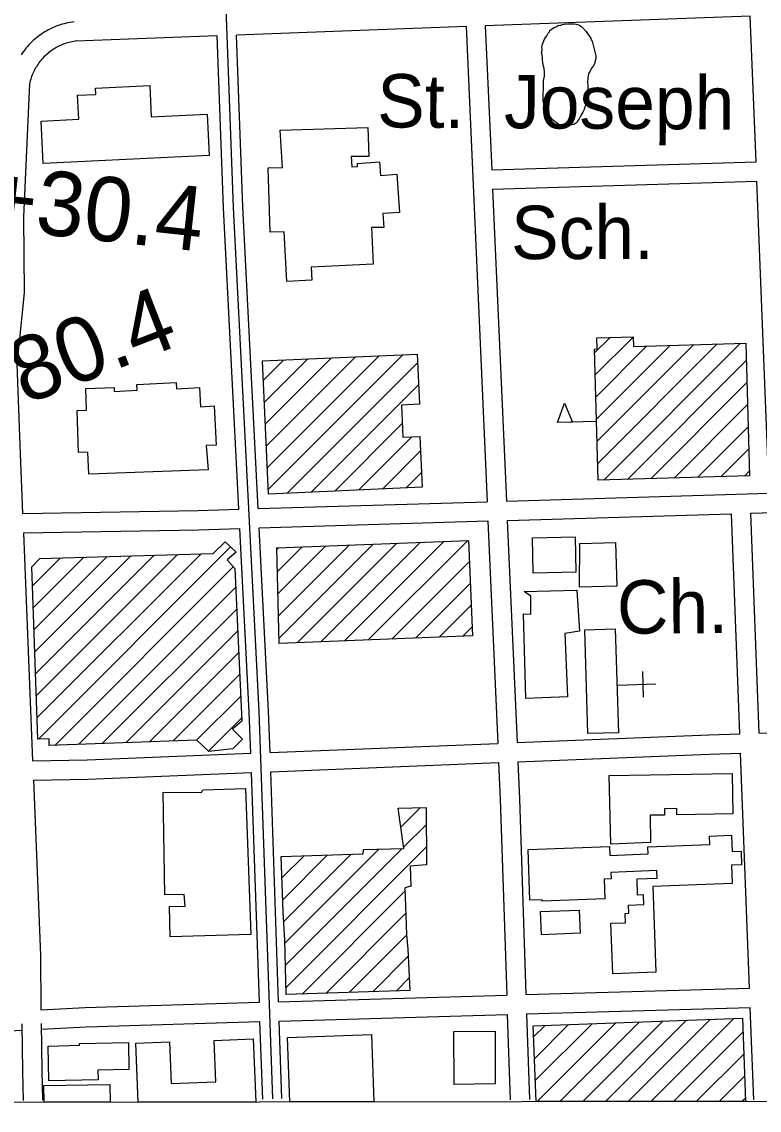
# Model space of a CAD drawing. Extents: x 3313447 to 3351316, y 703786 to 729172.
# Drawn here: x 3326147 to 3327294, y 709166 to 710857 of the extents above; entities that cross this region are included whole.
import ezdxf

# ---------------------------------------------------------------- set-up
doc = ezdxf.new("R2010")
doc.units = 0
for name, color, linetype in [('V-BLDG-IDEN', 7, 'Continuous'), ('V-BLDG-OTLN', 7, 'Continuous'), ('V-GRID-FRAM', 7, 'Continuous'), ('V-ROAD-CNTR', 7, 'Continuous'), ('V-SITE-OTLN', 7, 'Continuous'), ('V-SITE-OTLN-IDEN', 7, 'Continuous'), ('V-SITE-VEGE', 7, 'Continuous'), ('V-SURV-IDEN', 7, 'Continuous')]:
    doc.layers.add(name, color=color, linetype=linetype)

msp = doc.modelspace()

# ---------------------------------------------------------------- linework, layer by layer
at = {"layer": 'V-BLDG-OTLN'}
for p, q in [((3327037.8, 710343), (3327061.8, 710367)), ((3327038.8, 710308.6), (3327097.6, 710367.5)), ((3327040.7, 710239.9), (3327155.6, 710354.7)), ((3327041.7, 710205.5), (3327192, 710355.8)), ((3327042.7, 710171.2), (3327228.4, 710356.8)), ((3327052.2, 710145.3), (3327264.8, 710357.9)), ((3326528.8, 710164.4), (3326702.9, 710338.5)), ((3326530.3, 710130.5), (3326739.9, 710340.1)), ((3327039.8, 710274.3), (3327119.2, 710353.7)), ((3326522.7, 710299.8), (3326554.9, 710331.9)), ((3326524.2, 710265.9), (3326591.9, 710333.6)), ((3326525.7, 710232.1), (3326628.9, 710335.2)), ((3326527.2, 710198.2), (3326665.9, 710336.9)), ((3326559.9, 710124.8), (3326762.7, 710327.7)), ((3327088.7, 710146.4), (3327273.5, 710331.3)), ((3326596.9, 710126.5), (3326764.3, 710293.8)), ((3327125.1, 710147.4), (3327274.5, 710296.9)), ((3327161.5, 710148.5), (3327275.5, 710262.5)), ((3327040.3, 710236.3), (3326980.3, 710234.6)), ((3326633.9, 710128.1), (3326738.8, 710233)), ((3327197.9, 710149.5), (3327276.5, 710228.2)), ((3326670.9, 710129.8), (3326753.5, 710212.4)), ((3326707.9, 710131.4), (3326767.3, 710190.8)), ((3327234.3, 710150.6), (3327277.5, 710193.8)), ((3326744.9, 710133.1), (3326768.8, 710156.9)), ((3327270.7, 710151.6), (3327278.5, 710159.5)), ((3326648.9, 709895.3), (3326803.8, 710050.1)), ((3326685.7, 709896.8), (3326840.5, 710051.6)), ((3326173.1, 709742.7), (3326471.9, 710041.5)), ((3326543.7, 710037.6), (3326546.2, 710040.1)), ((3326544.6, 710003.1), (3326583, 710041.5)), ((3326545.5, 709968.7), (3326619.8, 710043)), ((3326546.4, 709934.2), (3326656.6, 710044.4)), ((3326547.3, 709899.7), (3326693.4, 710045.8)), ((3326575.2, 709892.3), (3326730.2, 710047.3)), ((3326612.1, 709893.8), (3326767, 710048.7)), ((3326163.9, 709980.9), (3326207.3, 710024.4)), ((3326165.1, 709946.8), (3326243.7, 710025.4)), ((3326166.2, 709912.6), (3326280.2, 710026.5)), ((3326167.4, 709878.4), (3326316.6, 710027.6)), ((3326168.6, 709844.2), (3326353, 710028.6)), ((3326169.8, 709810), (3326389.4, 710029.7)), ((3326170.9, 709775.9), (3326425.9, 710030.8)), ((3326722.6, 709898.2), (3326843.2, 710018.9)), ((3326198.8, 709733), (3326476.1, 710010.3)), ((3326759.4, 709899.7), (3326844.6, 709984.9)), ((3326235.5, 709734.4), (3326479.8, 709978.7)), ((3326796.2, 709901.2), (3326846.1, 709951)), ((3326272.2, 709735.7), (3326481.4, 709944.9)), ((3326833.1, 709902.7), (3326847.5, 709917.1)), ((3326309, 709737.1), (3326482.9, 709911.1)), ((3326345.7, 709738.4), (3326484.5, 709877.3)), ((3326382.4, 709739.8), (3326486, 709843.5)), ((3326419.1, 709741.1), (3326487.6, 709809.7)), ((3326437.3, 709724), (3326489.1, 709775.9)), ((3326736.6, 709606), (3326767, 709636.4)), ((3326740.8, 709574.8), (3326776.2, 709610.2)), ((3326551.8, 709527.2), (3326586.1, 709561.6)), ((3326553, 709493), (3326622.7, 709562.8)), ((3326554.5, 709459.2), (3326659.2, 709563.9)), ((3326556.2, 709425.6), (3326702.3, 709571.7)), ((3326557.2, 709391.2), (3326738.6, 709572.6)), ((3326558.1, 709356.8), (3326776.4, 709575.1)), ((3326750.5, 709513.8), (3326752, 709515.3)), ((3326583.1, 709346.4), (3326742.9, 709506.2)), ((3326619.7, 709347.6), (3326744.2, 709472.1)), ((3326656.2, 709348.8), (3326745.6, 709438.2)), ((3326692.8, 709350), (3326748, 709405.3)), ((3326729.3, 709351.2), (3326749.6, 709371.5)), ((3326942.4, 709297.2), (3327267.5, 709308.9)), ((3327054.7, 709179.8), (3327180.7, 709305.8)), ((3327090.1, 709179.8), (3327217.4, 709307.1)), ((3327125.5, 709179.9), (3327254.1, 709308.5)), ((3327267.5, 709308.9), (3327272.2, 709180.1)), ((3326946.7, 709179.6), (3326942.4, 709297.2)), ((3326943, 709280.2), (3326960.7, 709297.9)), ((3326944.2, 709246.1), (3326997.3, 709299.2)), ((3326945.5, 709212), (3327034, 709300.5)), ((3326948.5, 709179.6), (3327070.7, 709301.8)), ((3326983.9, 709179.7), (3327107.4, 709303.2)), ((3327019.3, 709179.7), (3327144.1, 709304.5)), ((3326324.6, 709270), (3326376.7, 709272.2)), ((3326376.7, 709272.2), (3326379.4, 709207.4)), ((3326446.5, 709274.5), (3326506.8, 709277)), ((3326449.1, 709210.2), (3326446.5, 709274.5)), ((3326506.8, 709277), (3326510.9, 709179)), ((3326560.2, 709278.9), (3326690.7, 709283.7)), ((3326563.9, 709179.1), (3326560.2, 709278.9)), ((3326690.7, 709283.7), (3326694.6, 709179.2)), ((3327160.9, 709179.9), (3327268.3, 709287.3)), ((3326328.3, 709178.7), (3326324.6, 709270)), ((3327196.3, 709180), (3327269.6, 709253.2)), ((3326181.7, 709204.5), (3326284.4, 709205.9)), ((3326182.1, 709178.5), (3326181.7, 709204.5)), ((3326284.4, 709205.9), (3326284.8, 709178.6)), ((3326379.4, 709207.4), (3326449.1, 709210.2)), ((3327231.7, 709180), (3327270.8, 709219.1)), ((3326284.8, 709178.6), (3326182.1, 709178.5)), ((3326510.9, 709179), (3326328.3, 709178.7)), ((3326694.6, 709179.2), (3326563.9, 709179.1)), ((3327272.2, 709180.1), (3326946.7, 709179.6)), ((3327267.1, 709180.1), (3327272, 709185))]:
    msp.add_line(p, q, dxfattribs=at)
for points in [[(3326438.8, 710649.7), (3326180.4, 710637.4), (3326177.2, 710703.2), (3326235.9, 710706), (3326234.1, 710743.2), (3326262.3, 710744.6), (3326261.8, 710754.4), (3326346.1, 710758.4), (3326348.4, 710709.9), (3326435.7, 710714.1)], [(3326548.9, 710689), (3326685.4, 710693.3), (3326686.8, 710648.3), (3326659.1, 710648.2), (3326660.2, 710632), (3326669.4, 710632.6), (3326669.1, 710637.3), (3326703.4, 710639.7), (3326704.9, 710618.8), (3326730.2, 710620.6), (3326734.3, 710561.3), (3326708.4, 710559.5), (3326709.9, 710537.8), (3326691.1, 710537.6), (3326693.7, 710480.7), (3326597.4, 710476.2), (3326598.3, 710455.8), (3326559.5, 710454), (3326555.4, 710531.1), (3326533.2, 710530.4), (3326530.1, 710630.4), (3326552.5, 710631.1)], [(3327272.8, 710358.1), (3327278.7, 710151.9), (3327043.5, 710145.1), (3327037.6, 710348.9), (3327041.5, 710349), (3327041, 710366.4), (3327097.6, 710368), (3327098, 710353.1)], [(3326769.8, 710134.2), (3326530.6, 710123.5), (3326521.4, 710330.4), (3326762.1, 710341.1), (3326765.6, 710263), (3326737.6, 710261.8), (3326739.8, 710211.8), (3326766.3, 710213)], [(3326437.1, 710161), (3326251.3, 710154.6), (3326250, 710188.7), (3326235.7, 710188.2), (3326233.6, 710253.6), (3326248, 710254.1), (3326246.9, 710287.5), (3326290.8, 710288.9), (3326290.8, 710283.1), (3326326.5, 710284.9), (3326326, 710293.7), (3326387.2, 710296.8), (3326387.7, 710287.1), (3326423.7, 710289), (3326425.2, 710259.3), (3326446.4, 710260.4), (3326449.5, 710199.7), (3326433.9, 710198.8)], [(3326980.3, 710234.6), (3326991, 710264.9), (3327003.4, 710235.2)], [(3326543.7, 710040), (3326841.8, 710051.6), (3326848.1, 709903.3), (3326547.5, 709891.2)], [(3326941, 710055.5), (3327007.5, 710057), (3327008.8, 710002.1), (3326942.1, 710000.6)], [(3326172.1, 709742.6), (3326162.9, 710010.7), (3326175.3, 710023.4), (3326444.7, 710031.3), (3326463.6, 710049.1), (3326480.8, 710033.4), (3326466.4, 710021.4), (3326478.5, 710007.7), (3326489.4, 709770.5), (3326475.1, 709758.4), (3326490.3, 709742.8), (3326475.3, 709727.5), (3326437.9, 709723.5), (3326419.4, 709741.2), (3326190, 709732.7), (3326189.6, 709743.2)], [(3327014.6, 710046.6), (3327070.4, 710048.2), (3327072.4, 709980.4), (3327014.4, 709978.7)], [(3326930.7, 709805.9), (3326927.4, 709937.2), (3326938.7, 709937), (3326938.4, 709964.9), (3326928.5, 709972.3), (3327010.2, 709974.3), (3327014.5, 709910.5), (3326991.4, 709906.7), (3326995.5, 709808.2)], [(3327070, 709913.9), (3327074.7, 709752.7), (3327027.1, 709751.3), (3327022.4, 709912.8)], [(3327063, 709579.6), (3327060.3, 709686.4), (3327251.8, 709689.3), (3327252.8, 709626.6), (3327165.6, 709625.3), (3327165.6, 709634.7), (3327146.4, 709634.6), (3327146.5, 709624.6), (3327124.2, 709624.5), (3327124.5, 709582.3)], [(3326428.7, 709663.8), (3326495.2, 709666), (3326503.3, 709438.9), (3326378.2, 709435.4), (3326376.7, 709482.7), (3326401.1, 709483.2), (3326399.9, 709501.1), (3326369.9, 709500.9), (3326366.9, 709660.5), (3326426.5, 709659.7)], [(3326550.6, 709560.4), (3326677.9, 709564.6), (3326678.3, 709571.1), (3326741.1, 709572.6), (3326732.6, 709635.5), (3326776.1, 709636.6), (3326776.6, 709547.3), (3326751, 709545.3), (3326752, 709514.2), (3326742.7, 709511.6), (3326745.5, 709439.2), (3326747.6, 709416.1), (3326750.5, 709351.9), (3326558.4, 709345.6), (3326556.1, 709430.4), (3326553.6, 709474.2)], [(3326934.4, 709571.3), (3327060.9, 709576), (3327061.5, 709562), (3327120.9, 709564.2), (3327120.5, 709575.4), (3327216.7, 709579), (3327216.2, 709592), (3327250.6, 709593.3), (3327251.6, 709567.9), (3327265.4, 709568.4), (3327266.2, 709547.4), (3327250.8, 709546.9), (3327251.8, 709518.1), (3327128.2, 709513.5), (3327133.1, 709380.7), (3327066, 709378.2), (3327063.1, 709456.5), (3327085.8, 709457.3), (3327085.2, 709471.9), (3327091.1, 709472.1), (3327090.7, 709484.7), (3327114.5, 709485.6), (3327114, 709500.8), (3327104.6, 709500.4), (3327103.7, 709525.6), (3327135, 709526.8), (3327134.5, 709538.3), (3327063.2, 709535.7), (3327063.5, 709525.6), (3327052.4, 709525.2), (3327053.5, 709494.5), (3326956.4, 709490.9), (3326956.3, 709493.2), (3326937.3, 709492.4)], [(3327015.5, 709441.1), (3326955, 709438.8), (3326953.6, 709474.6), (3327013.8, 709476.9)], [(3326819.3, 709206), (3326818.9, 709288.6), (3326883, 709288.9), (3326883.4, 709207.1)], [(3326265.9, 709213.3), (3326189.3, 709211.6), (3326188.1, 709265.8), (3326237, 709266.9), (3326236.9, 709269.7), (3326313, 709271.4), (3326313.9, 709229.5), (3326265.6, 709228.4)]]:
    msp.add_lwpolyline(points, close=True, dxfattribs=at)
at = {"layer": 'V-GRID-FRAM'}
msp.add_lwpolyline([(3317576.9, 727351), (3317595.4, 709166), (3349105.8, 709211.8), (3349071.4, 727396.8), (3317576.9, 727351)], dxfattribs=at)
at = {"layer": 'V-ROAD-CNTR'}
for points in [[(3326425.2, 711947.6), (3326476, 710569.1), (3326516, 709785.5), (3326536.8, 709183.7)], [(3327279.7, 710866.4), (3326867.9, 710851.3)], [(3327288.7, 710639.7), (3327279.7, 710866.4)], [(3326228.9, 710857.4), (3326225.9, 710857), (3326222.7, 710856.5), (3326219.5, 710855.9), (3326216.3, 710855.2), (3326213.2, 710854.5), (3326210, 710853.6), (3326206.9, 710852.6), (3326203.9, 710851.6), (3326200.8, 710850.5), (3326197.8, 710849.2), (3326194.8, 710847.9), (3326191.9, 710846.6), (3326189, 710845.1), (3326186.1, 710843.5), (3326183.3, 710841.9), (3326180.5, 710840.2), (3326177.8, 710838.4), (3326175.1, 710836.6), (3326172.5, 710834.6), (3326170, 710832.6), (3326167.5, 710830.5), (3326165, 710828.4), (3326162.7, 710826.1), (3326160.3, 710823.9), (3326158.1, 710821.5), (3326155.9, 710819.1), (3326153.8, 710816.6), (3326151.8, 710814.1), (3326149.8, 710811.5), (3326147.9, 710808.9), (3326146.1, 710806.2)], [(3326837.9, 710850.2), (3326769.7, 710847.7), (3326481.1, 710836.9)], [(3326837.9, 710850.2), (3326870.6, 710111.6)], [(3326867.9, 710851.3), (3326877.8, 710627.4)], [(3326232.8, 710827.7), (3326230.2, 710827.3), (3326227.8, 710827), (3326225.5, 710826.5), (3326223.1, 710826), (3326220.8, 710825.4), (3326218.5, 710824.8), (3326216.2, 710824.1), (3326213.9, 710823.3), (3326211.6, 710822.5), (3326209.4, 710821.6), (3326207.2, 710820.6), (3326205, 710819.6), (3326202.9, 710818.5), (3326200.8, 710817.4), (3326198.7, 710816.2), (3326196.6, 710814.9), (3326194.6, 710813.6), (3326192.7, 710812.2), (3326190.7, 710810.8), (3326188.8, 710809.3), (3326187, 710807.7), (3326185.2, 710806.2), (3326183.4, 710804.5), (3326181.7, 710802.8), (3326180.1, 710801.1), (3326178.5, 710799.3), (3326176.9, 710797.5), (3326175.4, 710795.6), (3326173.9, 710793.7), (3326172.5, 710791.7), (3326171.2, 710789.7), (3326169.9, 710787.7), (3326168.7, 710785.7), (3326167.5, 710783.6), (3326166.4, 710781.4), (3326165.4, 710779.3), (3326164.4, 710777.1), (3326163.4, 710774.9), (3326162.6, 710772.6), (3326161.8, 710770.3), (3326161.1, 710768.1), (3326160.4, 710765.7), (3326159.8, 710763.4), (3326159.2, 710761.1), (3326158.8, 710759)], [(3326451.1, 710835.8), (3326231.4, 710827.6)], [(3326484.9, 710100.1), (3326461, 710568.5), (3326451.1, 710835.8)], [(3326514.9, 710101), (3326491, 710569.8), (3326481.1, 710836.9)], [(3326159.1, 710761.3), (3326149.7, 710553.8), (3326151.1, 710436.5), (3326144.1, 710370.1), (3326139.6, 710325.3), (3326144.2, 710199.3), (3326148.5, 710093.5)], [(3326877.8, 710627.4), (3327288.7, 710639.7)], [(3326879.1, 710597.4), (3327289.9, 710609.7)], [(3327309.3, 710124.8), (3327289.9, 710609.7)], [(3326879.1, 710597.4), (3326900.6, 710112.5)], [(3326900.6, 710112.5), (3327309.3, 710124.8)], [(3326514.9, 710101), (3326870.6, 710111.6)], [(3327280.7, 710093.9), (3327405.7, 710097.6), (3327621.8, 710106.9)], [(3326148.5, 710093.5), (3326421.4, 710098.2), (3326484.9, 710100.1)], [(3326901.9, 710082.6), (3327250.7, 710093)], [(3327263.7, 709750.9), (3327250.7, 710093)], [(3327293.7, 709751.8), (3327280.7, 710093.9)], [(3326149.7, 710063.5), (3326422.1, 710068.2), (3326486.5, 710070.1)], [(3326503.2, 709720.7), (3326501, 709784.8), (3326486.5, 710070.1)], [(3326516.4, 710071), (3326871.9, 710081.7)], [(3326533.2, 709721.9), (3326531, 709786.1), (3326516.4, 710071)], [(3326871.9, 710081.7), (3326887.2, 709736.1)], [(3326901.9, 710082.6), (3326917.2, 709737.3)], [(3326149.7, 710063.5), (3326164.1, 709708.8)], [(3327293.7, 709751.8), (3327634.6, 709762.9)], [(3326917.2, 709737.3), (3327215.1, 709749.3), (3327263.7, 709750.9)], [(3326533.2, 709721.9), (3326887.2, 709736.1)], [(3326164.1, 709708.8), (3326248.8, 709710.5), (3326503.2, 709720.7)], [(3326918.5, 709707.4), (3327216.2, 709719.3), (3327264.8, 709720.9)], [(3327278.7, 709355.9), (3327264.8, 709720.9)], [(3326534.3, 709692), (3326888.5, 709706.2)], [(3326888.5, 709706.2), (3326891, 709648.8), (3326901.1, 709344.9)], [(3326918.5, 709707.4), (3326921, 709650), (3326931.1, 709345.8)], [(3326165.3, 709678.9), (3326249.7, 709680.6), (3326504.3, 709690.8)], [(3326165.3, 709678.9), (3326176.3, 709407.1), (3326177.1, 709322.1)], [(3326516.6, 709333.7), (3326504.3, 709690.8)], [(3326546.6, 709334.5), (3326534.3, 709692)], [(3326546.6, 709334.5), (3326901.1, 709344.9)], [(3326931.1, 709345.8), (3327278.7, 709355.9)], [(3326177.1, 709322.1), (3326245.9, 709325.8), (3326516.6, 709333.7)], [(3326932.1, 709315.8), (3327279.8, 709325.9)], [(3327285.2, 709182.4), (3327279.8, 709325.9)], [(3326547.6, 709304.6), (3326902.1, 709314.9)], [(3326902.1, 709314.9), (3326906.5, 709182)], [(3326932.1, 709315.8), (3326936.5, 709182.9)], [(3325849.4, 709274.3), (3326147.4, 709290.4)], [(3326147.3, 709300.5), (3326147.3, 709300.5), (3326148.4, 709226.9), (3326149.6, 709181)], [(3326177.3, 709300.8), (3326177.3, 709300.8), (3326178.4, 709227.5), (3326179.6, 709181.7)], [(3326177.4, 709292), (3326247.2, 709295.8), (3326517.6, 709303.7)], [(3326521.8, 709183.1), (3326517.6, 709303.7)], [(3326551.8, 709184.2), (3326547.6, 709304.6)]]:
    msp.add_lwpolyline(points, dxfattribs=at)
at = {"layer": 'V-SITE-OTLN'}
for p, q in [((3327113.9, 709807.9), (3327112.5, 709847.9)), ((3327073.2, 709826.5), (3327133.2, 709828.6))]:
    msp.add_line(p, q, dxfattribs=at)
at = {"layer": 'V-SITE-VEGE'}
msp.add_lwpolyline([(3327039.8, 710804.4), (3327039.8, 710801.7), (3327037.6, 710792.1), (3327035.5, 710788.7), (3327032.7, 710785.3), (3327032, 710783.3), (3327030.5, 710779.8), (3327028.4, 710777.1), (3327027, 710770.3), (3327026.9, 710762), (3327027.5, 710760), (3327027.3, 710742.8), (3327025.9, 710740.1), (3327025.1, 710736), (3327024.4, 710733.9), (3327024.4, 710730.5), (3327022.9, 710726.4), (3327021.5, 710720.9), (3327019.4, 710716.8), (3327016.5, 710712), (3327013.7, 710706.6), (3327012.3, 710704.5), (3327010.2, 710701.1), (3327005.4, 710697.8), (3327003.3, 710697.8), (3326998.5, 710696.5), (3326988.2, 710696.6), (3326986.1, 710697.3), (3326983.4, 710697.4), (3326980, 710699.5), (3326972.5, 710705.1), (3326963.7, 710717.6), (3326962.4, 710719.6), (3326961.1, 710724.5), (3326959.7, 710726.5), (3326959.1, 710730), (3326957.8, 710734.1), (3326958.2, 710764.3), (3326959, 710769.8), (3326959.7, 710771.9), (3326959.8, 710779.4), (3326959.2, 710784.9), (3326958.5, 710788.4), (3326957.2, 710793.9), (3326956.6, 710798.7), (3326956.6, 710800.8), (3326956, 710806.3), (3326955.4, 710809.7), (3326956.1, 710813.1), (3326955.5, 710818.6), (3326956.9, 710822.8), (3326957.7, 710825.5), (3326959.8, 710830.3), (3326961.2, 710833), (3326963.3, 710835.7), (3326965.4, 710839.8), (3326967.5, 710841.8), (3326968.2, 710843.9), (3326971, 710845.9), (3326975.1, 710848.6), (3326979.3, 710849.9), (3326981.4, 710852), (3326984.1, 710851.9), (3326987.6, 710853.2), (3326990.3, 710853.9), (3326996.5, 710854.5), (3327006.1, 710854.4), (3327008.9, 710853.6), (3327013, 710852.9), (3327017.7, 710849.4), (3327024.5, 710842.4), (3327028.6, 710836.2), (3327030.6, 710834.1), (3327031.9, 710832), (3327032.6, 710829.3), (3327033.9, 710827.2), (3327035.2, 710823.1)], close=True, dxfattribs=at)

# ---------------------------------------------------------------- texts
at = {"layer": 'V-BLDG-IDEN'}
msp.add_text('St.  Joseph', height=83, rotation=359.6345, dxfattribs=at).set_placement((3326699.5, 710693.4))
msp.add_text('Sch.', height=83, dxfattribs=at).set_placement((3326907.9, 710488.7))
at = {"layer": 'V-SITE-OTLN-IDEN'}
msp.add_text('Ch.', height=83, rotation=0.3995, dxfattribs=at).set_placement((3327072.7, 709906.4))
at = {"layer": 'V-SURV-IDEN'}
for s, rotation, p in [('31+30.4', 353.7175, (3325940.5, 710553.6)), ('36+80.4', 21.1558, (3325940.4, 710180))]:
    msp.add_text(s, height=100, rotation=rotation, dxfattribs=at).set_placement(p)

doc.saveas('drawing.dxf')
